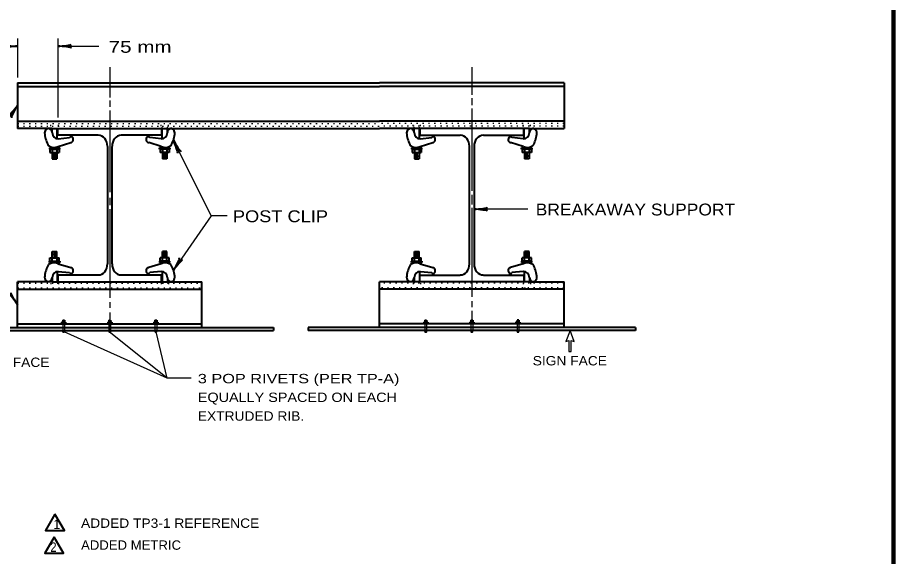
# Model space of a CAD drawing. Extents: x 851 to 1706, y -23 to 521.
# Drawn here: x 1475.1 to 1699.7, y 113.3 to 251.5 of the extents above; entities that cross this region are included whole.
import ezdxf
from ezdxf.enums import TextEntityAlignment as Align

# ---------------------------------------------------------------- set-up
doc = ezdxf.new("R2010")
doc.units = 0
doc.linetypes.add('DOTTED', pattern=[1.5, 0.3, -1.2])
doc.linetypes.add('SHORT_DASHED', pattern=[2.7, 1.5, -1.2])
doc.layers.add('1', color=7, linetype='Continuous', lineweight=35)

msp = doc.modelspace()

# ---------------------------------------------------------------- linework, layer by layer
at = {"layer": '1', "lineweight": 158}
msp.add_line((1699.744, -11.848), (1699.744, 514.252), dxfattribs=at)
at = {"layer": '1', "lineweight": 13}
msp.add_line((1699.744, -11.848), (1699.744, 514.252), dxfattribs=at)
at = {"layer": '1', "lineweight": 25}
for p, q in [((1475.115, 246.124), (1475.115, 236.117)), ((1485.46, 246.124), (1485.46, 225.863)), ((1463.149, 244.147), (1475.115, 244.147)), ((1485.46, 244.147), (1495.957, 244.147)), ((1498.761, 238.748), (1498.761, 231.016)), ((1591.621, 238.748), (1591.621, 231.65)), ((1498.761, 230.193), (1498.761, 228.576)), ((1591.621, 230.822), (1591.621, 229.049)), ((1498.761, 227.63), (1498.761, 206.762)), ((1591.621, 228.162), (1591.621, 207.057)), ((1498.761, 205.284), (1498.761, 203.392)), ((1591.621, 206.053), (1591.621, 203.57)), ((1456.404, 202.356), (1475.115, 177.854)), ((1498.761, 202.387), (1498.761, 179.628)), ((1591.621, 202.742), (1591.621, 179.923)), ((1605.987, 202.361), (1592.213, 202.361)), ((1524.776, 200.636), (1515.088, 186.764)), ((1498.761, 178.505), (1498.761, 177.086)), ((1591.621, 178.741), (1591.621, 177.263)), ((1498.761, 175.904), (1498.761, 170.672)), ((1591.621, 176.317), (1591.621, 173.894)), ((1513.452, 159.055), (1487.053, 170.879)), ((1513.452, 159.055), (1498.65, 170.879))]:
    msp.add_line(p, q, dxfattribs=at)
at = {"layer": '1', "lineweight": 40}
for p, q in [((1475.115, 234.783), (1475.115, 223.078)), ((1475.115, 234.783), (1567.975, 234.783)), ((1475.115, 233.837), (1567.975, 233.837)), ((1615.268, 234.783), (1567.975, 234.783)), ((1615.268, 233.837), (1567.975, 233.837)), ((1615.268, 234.783), (1615.268, 223.078)), ((1475.115, 224.97), (1567.975, 224.97)), ((1615.268, 224.97), (1567.975, 224.97)), ((1483.982, 223.078), (1475.115, 223.078)), ((1483.982, 222.014), (1483.982, 223.078)), ((1483.982, 223.078), (1567.975, 223.078)), ((1485.312, 221.304), (1485.312, 223.078)), ((1485.312, 220.417), (1485.312, 223.078)), ((1512.209, 220.417), (1512.209, 223.078)), ((1513.54, 222.014), (1513.54, 223.078)), ((1606.4, 223.078), (1567.975, 223.078)), ((1576.843, 222.014), (1576.843, 223.078)), ((1578.173, 220.417), (1578.173, 223.078)), ((1605.07, 221.304), (1605.07, 223.078)), ((1605.07, 220.417), (1605.07, 223.078)), ((1606.4, 222.014), (1606.4, 223.078)), ((1606.4, 223.078), (1615.268, 223.078)), ((1485.509, 220.417), (1488.465, 220.713)), ((1511.964, 220.417), (1509.057, 220.713)), ((1578.37, 220.417), (1581.326, 220.713)), ((1604.824, 220.417), (1601.868, 220.713)), ((1483.292, 218.112), (1485.953, 218.112)), ((1483.292, 218.112), (1483.292, 217.757)), ((1485.509, 218.408), (1488.76, 219.472)), ((1485.953, 217.757), (1485.953, 218.112)), ((1498.17, 218.467), (1498.17, 188.318)), ((1499.352, 188.318), (1499.352, 218.467)), ((1511.964, 218.408), (1508.761, 219.472)), ((1514.18, 218.112), (1511.52, 218.112)), ((1511.52, 217.757), (1511.52, 218.112)), ((1514.18, 218.112), (1514.18, 217.757)), ((1576.153, 218.112), (1578.813, 218.112)), ((1576.153, 218.112), (1576.153, 217.757)), ((1578.37, 218.408), (1581.621, 219.472)), ((1578.813, 217.757), (1578.813, 218.112)), ((1591.03, 188.318), (1591.03, 218.467)), ((1592.213, 218.467), (1592.213, 188.318)), ((1604.824, 218.408), (1601.573, 219.472)), ((1607.041, 218.112), (1604.381, 218.112)), ((1604.381, 217.757), (1604.381, 218.112)), ((1607.041, 218.112), (1607.041, 217.757)), ((1483.292, 217.757), (1485.953, 217.757)), ((1483.44, 217.757), (1483.44, 216.871)), ((1483.44, 216.871), (1485.804, 216.871)), ((1484.031, 217.757), (1484.031, 216.871)), ((1484.031, 216.871), (1484.031, 215.275)), ((1484.031, 215.984), (1485.213, 215.984)), ((1484.327, 216.441), (1484.918, 216.441)), ((1485.213, 217.757), (1485.213, 216.871)), ((1485.213, 216.871), (1485.213, 215.275)), ((1485.804, 217.757), (1485.804, 216.871)), ((1514.18, 217.757), (1511.52, 217.757)), ((1511.668, 217.757), (1511.668, 216.871)), ((1514.032, 216.871), (1511.668, 216.871)), ((1512.259, 217.757), (1512.259, 216.871)), ((1512.259, 216.871), (1512.259, 215.275)), ((1513.441, 215.984), (1512.259, 215.984)), ((1513.146, 216.439), (1512.554, 216.439)), ((1513.441, 217.757), (1513.441, 216.871)), ((1513.441, 216.871), (1513.441, 215.275)), ((1514.032, 217.757), (1514.032, 216.871)), ((1576.153, 217.757), (1578.813, 217.757)), ((1576.301, 217.757), (1576.301, 216.871)), ((1576.301, 216.871), (1578.666, 216.871)), ((1576.892, 217.757), (1576.892, 216.871)), ((1576.892, 216.871), (1576.892, 215.275)), ((1576.892, 215.984), (1578.074, 215.984)), ((1577.188, 216.425), (1577.779, 216.425)), ((1578.074, 217.757), (1578.074, 216.871)), ((1578.074, 216.871), (1578.074, 215.275)), ((1578.666, 217.757), (1578.666, 216.871)), ((1607.041, 217.757), (1604.381, 217.757)), ((1604.528, 217.757), (1604.528, 216.871)), ((1606.893, 216.871), (1604.528, 216.871)), ((1605.12, 217.757), (1605.12, 216.871)), ((1605.12, 216.871), (1605.12, 215.275)), ((1606.302, 215.984), (1605.12, 215.984)), ((1606.007, 216.421), (1605.415, 216.421)), ((1606.302, 217.757), (1606.302, 216.871)), ((1606.302, 216.871), (1606.302, 215.275)), ((1606.893, 217.757), (1606.893, 216.871)), ((1484.031, 215.275), (1485.213, 215.275)), ((1484.327, 215.629), (1484.918, 215.629)), ((1513.441, 215.275), (1512.259, 215.275)), ((1513.146, 215.629), (1512.554, 215.629)), ((1576.892, 215.275), (1578.074, 215.275)), ((1577.188, 215.629), (1577.779, 215.629)), ((1606.302, 215.275), (1605.12, 215.275)), ((1606.007, 215.629), (1605.415, 215.629)), ((1484.031, 191.51), (1485.213, 191.51)), ((1484.031, 189.914), (1484.031, 191.51)), ((1484.327, 191.155), (1484.918, 191.155)), ((1485.213, 189.914), (1485.213, 191.51)), ((1513.441, 191.51), (1512.259, 191.51)), ((1512.259, 189.914), (1512.259, 191.51)), ((1513.146, 191.155), (1512.554, 191.155)), ((1513.441, 189.914), (1513.441, 191.51)), ((1576.892, 191.51), (1578.074, 191.51)), ((1576.892, 189.914), (1576.892, 191.51)), ((1577.188, 191.155), (1577.779, 191.155)), ((1578.074, 189.914), (1578.074, 191.51)), ((1606.302, 191.51), (1605.12, 191.51)), ((1605.12, 189.914), (1605.12, 191.51)), ((1606.007, 191.155), (1605.415, 191.155)), ((1606.302, 189.914), (1606.302, 191.51)), ((1483.292, 189.027), (1485.953, 189.027)), ((1483.292, 188.673), (1483.292, 189.027)), ((1483.44, 189.027), (1483.44, 189.914)), ((1483.44, 189.914), (1485.804, 189.914)), ((1484.031, 190.8), (1485.213, 190.8)), ((1484.031, 189.027), (1484.031, 189.914)), ((1484.327, 190.329), (1484.918, 190.329)), ((1485.288, 189.027), (1485.288, 189.914)), ((1485.804, 189.027), (1485.804, 189.914)), ((1485.953, 189.027), (1485.953, 188.673)), ((1514.18, 189.027), (1511.52, 189.027)), ((1511.52, 189.027), (1511.52, 188.673)), ((1511.668, 189.027), (1511.668, 189.914)), ((1514.032, 189.914), (1511.668, 189.914)), ((1513.441, 190.8), (1512.259, 190.8)), ((1512.259, 189.027), (1512.259, 189.914)), ((1513.146, 190.338), (1512.554, 190.338)), ((1513.441, 189.027), (1513.441, 189.914)), ((1514.032, 189.027), (1514.032, 189.914)), ((1514.18, 188.673), (1514.18, 189.027)), ((1576.153, 189.027), (1578.813, 189.027)), ((1576.153, 188.673), (1576.153, 189.027)), ((1576.301, 189.027), (1576.301, 189.914)), ((1576.301, 189.914), (1578.666, 189.914)), ((1576.892, 190.8), (1578.074, 190.8)), ((1576.892, 189.027), (1576.892, 189.914)), ((1577.188, 190.36), (1577.779, 190.36)), ((1578.074, 189.027), (1578.074, 189.914)), ((1578.666, 189.027), (1578.666, 189.914)), ((1578.813, 189.027), (1578.813, 188.673)), ((1607.041, 189.027), (1604.381, 189.027)), ((1604.381, 189.027), (1604.381, 188.673)), ((1604.528, 189.027), (1604.528, 189.914)), ((1606.893, 189.914), (1604.528, 189.914)), ((1606.302, 190.8), (1605.12, 190.8)), ((1605.12, 189.027), (1605.12, 189.914)), ((1606.007, 190.361), (1605.415, 190.361)), ((1606.302, 189.027), (1606.302, 189.914)), ((1606.893, 189.027), (1606.893, 189.914)), ((1607.041, 188.673), (1607.041, 189.027)), ((1483.292, 188.673), (1485.953, 188.673)), ((1485.312, 188.673), (1485.312, 188.479)), ((1485.509, 188.377), (1488.76, 187.372)), ((1511.964, 188.377), (1508.761, 187.372)), ((1514.18, 188.673), (1511.52, 188.673)), ((1576.153, 188.673), (1578.813, 188.673)), ((1578.37, 188.377), (1581.621, 187.372)), ((1604.824, 188.377), (1601.573, 187.372)), ((1607.041, 188.673), (1604.381, 188.673)), ((1483.982, 184.771), (1483.982, 183.707)), ((1485.312, 186.393), (1485.312, 183.707)), ((1485.312, 185.48), (1485.312, 183.707)), ((1485.509, 186.426), (1488.465, 186.13)), ((1511.964, 186.426), (1509.057, 186.13)), ((1512.209, 186.367), (1512.209, 183.707)), ((1513.54, 184.771), (1513.54, 183.707)), ((1576.843, 184.771), (1576.843, 183.707)), ((1578.173, 186.367), (1578.173, 183.707)), ((1578.37, 186.426), (1581.326, 186.13)), ((1604.824, 186.426), (1601.868, 186.13)), ((1605.07, 186.367), (1605.07, 183.707)), ((1605.07, 185.48), (1605.07, 183.707)), ((1606.4, 184.771), (1606.4, 183.707)), ((1483.982, 183.707), (1475.115, 183.707)), ((1475.115, 172.002), (1475.115, 183.707)), ((1483.982, 183.707), (1522.407, 183.707)), ((1522.407, 172.002), (1522.407, 183.707)), ((1606.4, 183.707), (1567.975, 183.707)), ((1567.975, 172.002), (1567.975, 183.707)), ((1606.4, 183.707), (1615.268, 183.707)), ((1615.268, 172.002), (1615.268, 183.707)), ((1475.115, 181.874), (1522.407, 181.874)), ((1615.268, 181.874), (1567.975, 181.874)), ((1475.115, 173.007), (1522.407, 173.007)), ((1486.42, 173.427), (1487.455, 173.427)), ((1486.42, 173.427), (1486.42, 173.014)), ((1486.716, 173.9), (1486.716, 173.014)), ((1486.716, 173.9), (1487.159, 173.9)), ((1487.159, 173.9), (1487.159, 173.014)), ((1487.455, 173.427), (1487.455, 173.014)), ((1498.239, 173.427), (1499.274, 173.427)), ((1498.239, 173.427), (1498.239, 173.014)), ((1498.535, 173.9), (1498.535, 173.014)), ((1498.535, 173.9), (1498.978, 173.9)), ((1498.978, 173.9), (1498.978, 173.014)), ((1499.274, 173.427), (1499.274, 173.014)), ((1510.067, 173.427), (1511.101, 173.427)), ((1510.067, 173.427), (1510.067, 173.014)), ((1510.362, 173.9), (1510.362, 173.014)), ((1510.362, 173.9), (1510.806, 173.9)), ((1510.806, 173.9), (1510.806, 173.014)), ((1511.101, 173.427), (1511.101, 173.014)), ((1615.268, 173.007), (1567.975, 173.007)), ((1579.281, 173.421), (1580.316, 173.421)), ((1579.281, 173.421), (1579.281, 173.007)), ((1579.577, 173.894), (1579.577, 173.007)), ((1579.577, 173.894), (1580.02, 173.894)), ((1580.02, 173.894), (1580.02, 173.007)), ((1580.316, 173.421), (1580.316, 173.007)), ((1591.104, 173.421), (1592.139, 173.421)), ((1591.104, 173.421), (1591.104, 173.007)), ((1591.4, 173.894), (1591.4, 173.007)), ((1591.4, 173.894), (1591.843, 173.894)), ((1591.843, 173.894), (1591.843, 173.007)), ((1592.139, 173.421), (1592.139, 173.007)), ((1603.962, 173.421), (1602.928, 173.421)), ((1602.928, 173.421), (1602.928, 173.007)), ((1603.223, 173.894), (1603.223, 173.007)), ((1603.666, 173.894), (1603.223, 173.894)), ((1603.666, 173.894), (1603.666, 173.007)), ((1603.962, 173.421), (1603.962, 173.007)), ((1456.789, 172.002), (1540.733, 172.002)), ((1456.789, 171.233), (1540.733, 171.233)), ((1486.814, 170.886), (1487.061, 170.886)), ((1498.633, 170.886), (1498.88, 170.886)), ((1510.461, 170.886), (1510.707, 170.886)), ((1540.733, 172.002), (1540.733, 171.233)), ((1633.594, 172.002), (1549.649, 172.002)), ((1549.649, 172.002), (1549.649, 171.233)), ((1633.594, 171.233), (1549.649, 171.233)), ((1579.675, 170.879), (1579.922, 170.879)), ((1591.498, 170.879), (1591.745, 170.879)), ((1603.568, 170.879), (1603.371, 170.879)), ((1633.594, 172.002), (1633.594, 171.233))]:
    msp.add_line(p, q, dxfattribs=at)
at = {"layer": '1', "linetype": 'DOTTED', "lineweight": 25}
for p, q in [((1475.115, 224.312), (1567.975, 224.312)), ((1475.115, 223.654), (1483.982, 223.654)), ((1483.686, 223.654), (1483.686, 224.312)), ((1483.982, 223.654), (1485.46, 223.654)), ((1485.46, 223.654), (1512.209, 223.654)), ((1485.607, 223.654), (1485.607, 224.312)), ((1511.914, 223.654), (1511.914, 224.312)), ((1512.209, 223.078), (1512.209, 223.654)), ((1513.54, 223.078), (1513.54, 223.654)), ((1513.835, 223.654), (1513.835, 224.312)), ((1615.268, 224.312), (1567.975, 224.312)), ((1576.843, 223.654), (1567.975, 223.654)), ((1576.547, 223.654), (1576.547, 224.312)), ((1576.843, 223.078), (1576.843, 223.654)), ((1578.173, 223.654), (1576.843, 223.654)), ((1578.173, 223.078), (1578.173, 223.654)), ((1604.922, 223.654), (1578.173, 223.654)), ((1578.469, 223.654), (1578.469, 224.312)), ((1604.775, 223.654), (1604.775, 224.312)), ((1606.4, 223.654), (1604.922, 223.654)), ((1615.268, 223.654), (1606.4, 223.654)), ((1606.696, 223.654), (1606.696, 224.312)), ((1475.115, 183.411), (1483.982, 183.411)), ((1475.115, 182.229), (1522.407, 182.229)), ((1483.686, 183.411), (1483.686, 182.229)), ((1483.982, 183.411), (1485.312, 183.411)), ((1485.312, 183.411), (1512.209, 183.411)), ((1485.607, 183.411), (1485.607, 182.229)), ((1511.914, 183.411), (1511.914, 182.229)), ((1512.209, 183.707), (1512.209, 183.411)), ((1512.209, 183.411), (1513.54, 183.411)), ((1513.54, 183.707), (1513.54, 183.411)), ((1513.54, 183.411), (1522.407, 183.411)), ((1513.835, 183.411), (1513.835, 182.229)), ((1576.843, 183.411), (1567.975, 183.411)), ((1615.268, 182.229), (1567.975, 182.229)), ((1576.547, 183.411), (1576.547, 182.229)), ((1576.843, 183.707), (1576.843, 183.411)), ((1578.173, 183.411), (1576.843, 183.411)), ((1578.173, 183.707), (1578.173, 183.411)), ((1605.07, 183.411), (1578.173, 183.411)), ((1578.469, 183.411), (1578.469, 182.229)), ((1604.775, 183.411), (1604.775, 182.229)), ((1606.4, 183.411), (1605.07, 183.411)), ((1605.07, 182.229), (1606.4, 182.229)), ((1615.268, 183.411), (1606.4, 183.411)), ((1606.696, 183.411), (1606.696, 182.229))]:
    msp.add_line(p, q, dxfattribs=at)
at = {"layer": '1', "linetype": 'SHORT_DASHED', "lineweight": 25}
for p, q in [((1486.716, 173.014), (1486.716, 171.24)), ((1487.159, 173.014), (1487.159, 171.24)), ((1498.535, 173.014), (1498.535, 171.24)), ((1498.978, 173.014), (1498.978, 171.24)), ((1510.362, 173.014), (1510.362, 171.24)), ((1510.806, 173.014), (1510.806, 171.24)), ((1579.577, 173.007), (1579.577, 171.233)), ((1580.02, 173.007), (1580.02, 171.233)), ((1591.4, 173.007), (1591.4, 171.233)), ((1591.843, 173.007), (1591.843, 171.233)), ((1603.223, 173.007), (1603.223, 171.233)), ((1603.666, 173.007), (1603.666, 171.233))]:
    msp.add_line(p, q, dxfattribs=at)
at = {"layer": '1', "lineweight": 25}
for points in [[(1452.266, 202.356), (1456.404, 202.356), (1475.115, 228.93)], [(1528.914, 200.636), (1524.776, 200.636), (1515.088, 220.046)], [(1519.612, 159.055), (1513.452, 159.055), (1510.699, 170.879)]]:
    msp.add_lwpolyline(points, dxfattribs=at)
at = {"layer": '1', "lineweight": 40}
for points in [[(1495.805, 221.304), (1485.46, 221.304), (1485.46, 223.078)], [(1512.062, 223.078), (1512.062, 221.304), (1501.717, 221.304)], [(1578.321, 223.078), (1578.321, 221.304), (1588.666, 221.304)], [(1594.577, 221.304), (1604.922, 221.304), (1604.922, 223.078)], [(1495.805, 185.48), (1485.46, 185.48), (1485.46, 183.707)], [(1512.062, 183.707), (1512.062, 185.48), (1501.717, 185.48)], [(1578.321, 183.707), (1578.321, 185.48), (1588.666, 185.48)], [(1594.577, 185.48), (1604.922, 185.48), (1604.922, 183.707)]]:
    msp.add_lwpolyline(points, dxfattribs=at)
at = {"layer": '1', "linetype": 'DOTTED', "lineweight": 25}
msp.add_lwpolyline([(1512.209, 223.654), (1513.54, 223.654), (1567.975, 223.654)], dxfattribs=at)
at = {"layer": '1', "lineweight": 25}
msp.add_lwpolyline([(1616.805, 171.233), (1615.746, 168.401), (1616.534, 168.721), (1616.534, 165.913), (1617.076, 165.913), (1617.076, 168.721), (1617.864, 168.401)], close=True, dxfattribs=at)
at = {"layer": '1', "lineweight": 40}
for points in [[(1484.724, 124.175), (1482.324, 120.018), (1487.124, 120.018)], [(1484.479, 118.308), (1482.079, 114.151), (1486.879, 114.151)]]:
    msp.add_lwpolyline(points, close=True, dxfattribs=at)
for centre, major_axis, ratio, start_param, end_param in [((1473.805, 244.478), (2.143, -0.187), 0.122415, 3.1415927, 5.386832), ((1473.77, 243.893), (2.108, 0.211), 0.07063, 0.8650754, 3.1424706), ((1486.804, 244.401), (-2.108, -0.211), 0.07063, 0.8650754, 3.1424706), ((1486.769, 243.815), (-2.143, 0.187), 0.122415, 3.1415927, 5.386832), ((1474.133, 227.977), (1.386, 1.602), 0.07063, 3.1407148, 5.41811), ((1474.632, 227.669), (1.08, 1.86), 0.122415, 0.8963533, 3.1415927), ((1483.021, 221.873), (0, 1.155), 0.833333, 4.8456236, 8.1047466), ((1514.487, 221.873), (0, 1.155), 0.833333, 4.461624, 7.720747), ((1575.866, 221.873), (0, 1.155), 0.833333, 4.8456236, 8.1047466), ((1607.332, 221.873), (0, 1.155), 0.833333, 4.461624, 7.720747), ((1487.307, 222.379), (0, -6.311), 0.833333, 4.838237, 5.3438541), ((1485.459, 222.197), (0, -1.789), 0.833333, 4.8079877, 6.3294747), ((1488.874, 220.349), (0, 0.6), 0.833333, 5.7625855, 7.2478572), ((1488.775, 220.23), (0, -0.764), 0.833333, 6.2622547, 8.8459831), ((1495.798, 218.48), (0, 2.838), 0.833333, 4.712389, 6.2831853), ((1501.71, 218.48), (0, 2.838), 0.833333, 6.2831853, 7.8539816), ((1508.733, 220.23), (0, -0.764), 0.833333, 3.7203875, 6.3041159), ((1508.634, 220.349), (0, 0.6), 0.833333, 5.3185134, 6.8037851), ((1512.049, 222.197), (0, -1.789), 0.833333, 6.2368959, 7.7583829), ((1510.201, 222.379), (0, -6.311), 0.833333, 0.9393312, 1.4449483), ((1580.152, 222.379), (0, -6.311), 0.833333, 4.838237, 5.3438541), ((1578.304, 222.197), (0, -1.789), 0.833333, 4.8079877, 6.3294747), ((1581.72, 220.349), (0, 0.6), 0.833333, 5.7625855, 7.2478572), ((1581.62, 220.23), (0, -0.764), 0.833333, 6.2622547, 8.8459831), ((1588.643, 218.48), (0, 2.838), 0.833333, 4.712389, 6.2831853), ((1594.555, 218.48), (0, 2.838), 0.833333, 6.2831853, 7.8539816), ((1601.578, 220.23), (0, -0.764), 0.833333, 3.7203875, 6.3041159), ((1601.479, 220.349), (0, 0.6), 0.833333, 5.3185134, 6.8037851), ((1604.894, 222.197), (0, -1.789), 0.833333, 6.2368959, 7.7583829), ((1603.046, 222.379), (0, -6.311), 0.833333, 0.9393312, 1.4449483), ((1484.497, 221.61), (0, -3.421), 0.833333, 5.7557286, 6.6532497), ((1513.011, 221.61), (0, -3.421), 0.833333, 5.913121, 6.810642), ((1515.461, 218.729), (-0.753, 1.98), 0.07063, 3.1407148, 5.41811), ((1515.969, 219.022), (-1.125, 1.834), 0.122415, 0.8963533, 3.1415927), ((1577.342, 221.61), (0, -3.421), 0.833333, 5.7557286, 6.6532497), ((1605.856, 221.61), (0, -3.421), 0.833333, 5.913121, 6.810642), ((1593.557, 202.107), (-2.108, 0.211), 0.07063, 3.1407148, 5.41811), ((1593.522, 202.693), (-2.143, -0.187), 0.122415, 0.8963533, 3.1415927), ((1484.497, 185.201), (0, 3.421), 0.833333, 5.913121, 6.810642), ((1513.011, 185.201), (0, 3.421), 0.833333, 5.7557286, 6.6532497), ((1515.566, 188.028), (-1.073, -1.864), 0.122415, 0.8963533, 3.1415927), ((1516.066, 187.721), (-1.38, -1.607), 0.07063, 3.1407148, 5.41811), ((1577.342, 185.201), (0, 3.421), 0.833333, 5.913121, 6.810642), ((1605.856, 185.201), (0, 3.421), 0.833333, 5.7557286, 6.6532497), ((1487.307, 184.431), (0, 6.311), 0.833333, 0.9393312, 1.4449483), ((1485.459, 184.613), (0, 1.789), 0.833333, 6.2368959, 7.7583829), ((1488.775, 186.58), (0, 0.764), 0.833333, 3.7203875, 6.3041159), ((1495.798, 188.331), (0, -2.838), 0.833333, 6.2831853, 7.8539816), ((1501.71, 188.331), (0, -2.838), 0.833333, 4.712389, 6.2831853), ((1508.733, 186.58), (0, 0.764), 0.833333, 6.2622547, 8.8459831), ((1512.049, 184.613), (0, 1.789), 0.833333, 4.8079877, 6.3294747), ((1510.201, 184.431), (0, 6.311), 0.833333, 4.838237, 5.3438541), ((1580.152, 184.431), (0, 6.311), 0.833333, 0.9393312, 1.4449483), ((1578.304, 184.613), (0, 1.789), 0.833333, 6.2368959, 7.7583829), ((1581.62, 186.58), (0, 0.764), 0.833333, 3.7203875, 6.3041159), ((1588.643, 188.331), (0, -2.838), 0.833333, 6.2831853, 7.8539816), ((1594.555, 188.331), (0, -2.838), 0.833333, 4.712389, 6.2831853), ((1601.578, 186.58), (0, 0.764), 0.833333, 6.2622547, 8.8459831), ((1604.894, 184.613), (0, 1.789), 0.833333, 4.8079877, 6.3294747), ((1603.046, 184.431), (0, 6.311), 0.833333, 4.838237, 5.3438541), ((1483.021, 184.937), (0, -1.155), 0.833333, 4.461624, 7.720747), ((1488.874, 186.461), (0, -0.6), 0.833333, 5.3185134, 6.8037851), ((1508.634, 186.461), (0, -0.6), 0.833333, 5.7625855, 7.2478572), ((1514.487, 184.937), (0, -1.155), 0.833333, 4.8456236, 8.1047466), ((1575.866, 184.937), (0, -1.155), 0.833333, 4.461624, 7.720747), ((1581.72, 186.461), (0, -0.6), 0.833333, 5.3185134, 6.8037851), ((1601.479, 186.461), (0, -0.6), 0.833333, 5.7625855, 7.2478572), ((1607.332, 184.937), (0, -1.155), 0.833333, 4.8456236, 8.1047466), ((1474.5, 179.077), (1.112, -1.803), 0.07063, 3.1407148, 5.41811), ((1486.831, 171.233), (0, 0.355), 0.3125, 1.5707963, 4.712389), ((1487.053, 171.233), (0, 0.355), 0.3125, 1.5707963, 4.712389), ((1498.65, 171.233), (0, 0.355), 0.3125, 1.5707963, 4.712389), ((1498.872, 171.233), (0, 0.355), 0.3125, 1.5707963, 4.712389), ((1510.478, 171.233), (0, 0.355), 0.3125, 1.5707963, 4.712389), ((1510.699, 171.233), (0, 0.355), 0.3125, 1.5707963, 4.712389), ((1579.68, 171.227), (0, 0.355), 0.3125, 1.5707963, 4.712389), ((1579.901, 171.227), (0, 0.355), 0.3125, 1.5707963, 4.712389), ((1591.503, 171.227), (0, 0.355), 0.3125, 1.5707963, 4.712389), ((1591.724, 171.227), (0, 0.355), 0.3125, 1.5707963, 4.712389), ((1603.35, 171.227), (0, 0.355), 0.3125, 1.5707963, 4.712389), ((1603.571, 171.227), (0, 0.355), 0.3125, 1.5707963, 4.712389)]:
    msp.add_ellipse(centre, major_axis=major_axis, ratio=ratio, start_param=start_param, end_param=end_param, dxfattribs=at)

# ---------------------------------------------------------------- texts
at = {"layer": '1'}
for s, height, width, p in [('75 mm', 3.037, 1.3, (1506.554, 242.47)), ('BREAKAWAY SUPPORT', 3.037, 1.1, (1633.575, 200.756)), ('POST CLIP', 3.037, 1.15, (1542.536, 199.031)), ('SIGN FACE', 2.4, 1.1, (1473.8, 161.917)), ('SIGN FACE', 2.4, 1.1, (1616.746, 162.309)), ('ADDED TP3-1 REFERENCE', 2.4, 1.1, (1514.254, 120.666)), ('2', 2.4, 0.9, (1484.327, 114.514)), ('ADDED METRIC', 2.4, 1.05, (1504.234, 115.044))]:
    msp.add_text(s, height=height, dxfattribs=dict(at, width=width)).set_placement(p, align=Align.CENTER)
for s, width, p in [('3 POP RIVETS (PER TP-A) ', 1.3, (1521.357, 157.734)), ('EQUALLY SPACED ON EACH', 1.15, (1521.357, 152.934)), ('EXTRUDED RIB.', 1.1, (1521.357, 148.133))]:
    msp.add_text(s, height=2.4, dxfattribs=dict(at, width=width)).set_placement(p)
msp.add_text('1', height=2.4, dxfattribs=at).set_placement((1485.189, 120.381), align=Align.CENTER)

doc.saveas('drawing.dxf')
